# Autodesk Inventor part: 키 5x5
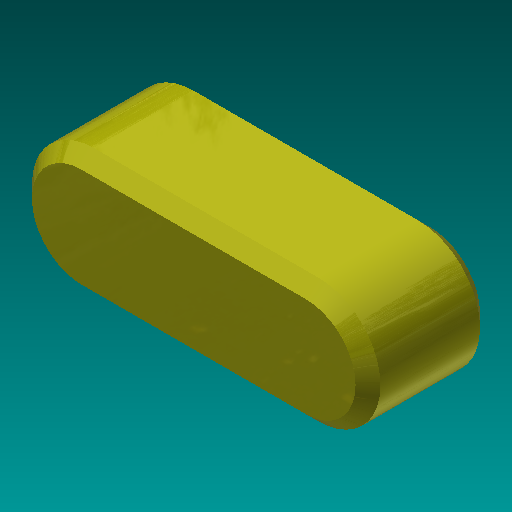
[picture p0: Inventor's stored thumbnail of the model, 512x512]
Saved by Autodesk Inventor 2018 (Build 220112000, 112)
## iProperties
Created: 2016-04
Part Number: 키 5x5
Document SubType Name: Modeling
Designer: mdu
Density: 7.86 g/cm^3
Mass: 2.54015 g
Surface Area: 2.9781 cm^2
Volume: 0.323175 cm^3
Material: 강철, 연강
Appearance: 노란색
Author: mdu
Revision Number: 1
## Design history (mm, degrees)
sketch "스케치1"
  geometry: L1 (-4.5, -2.5)-(4.5, -2.5); L2 (4.5, 2.5)-(-4.5, 2.5); A1 r 2.5 centre (4.5, 0) between (4.5, -2.5) and (4.5, 2.5); A2 r 2.5 centre (-4.5, 0) between (-4.5, 2.5) and (-4.5, -2.5); 2 further points
  constraints: 4 end point, 4 point on circle, 4 tangent, 2 centre point, 1 horizontal, 1 horizontal alignment, 1 midpoint, 1 parallel, 1 vertical alignment
  dimensions: "d0" = 5 distance between parallel lines of L1 L2; "d1" = 14 dimension on A1 A2
extrude "돌출1" new body sketch "스케치1" stored distance "d2" = 5; taper "d3" = 0 deg
chamfer "모따기1" distance "d4" = 0.5; stored, may be unused: second distance "d5" = 2, angle "d6" = 45 deg
node "솔리드1"
other parameters: "d0" = 5
